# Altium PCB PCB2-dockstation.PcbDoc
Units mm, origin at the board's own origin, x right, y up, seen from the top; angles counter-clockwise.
Board outline 98 x 71.5 mm, 2 copper layers (Top Layer, Bottom Layer), stack 1.4 mm thick; 17 components, 28 nets, 47 pads, 4 vias.
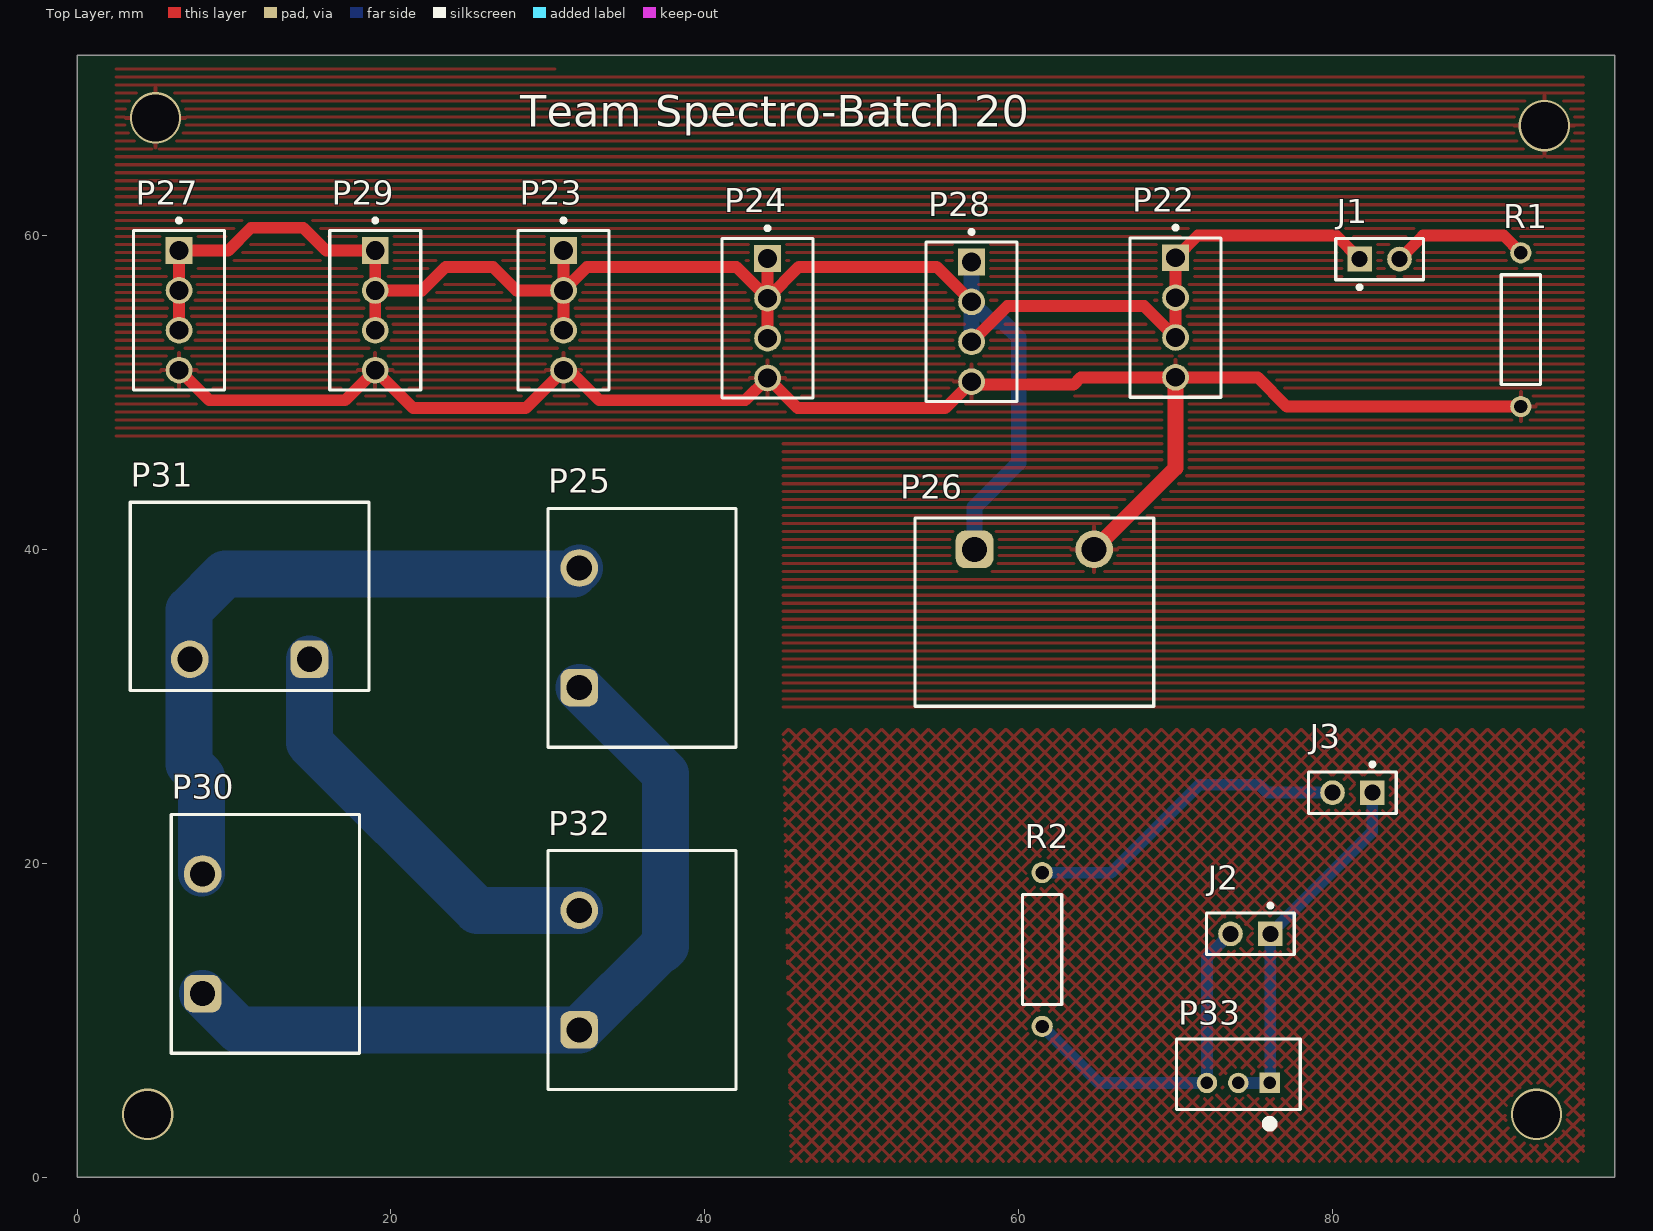
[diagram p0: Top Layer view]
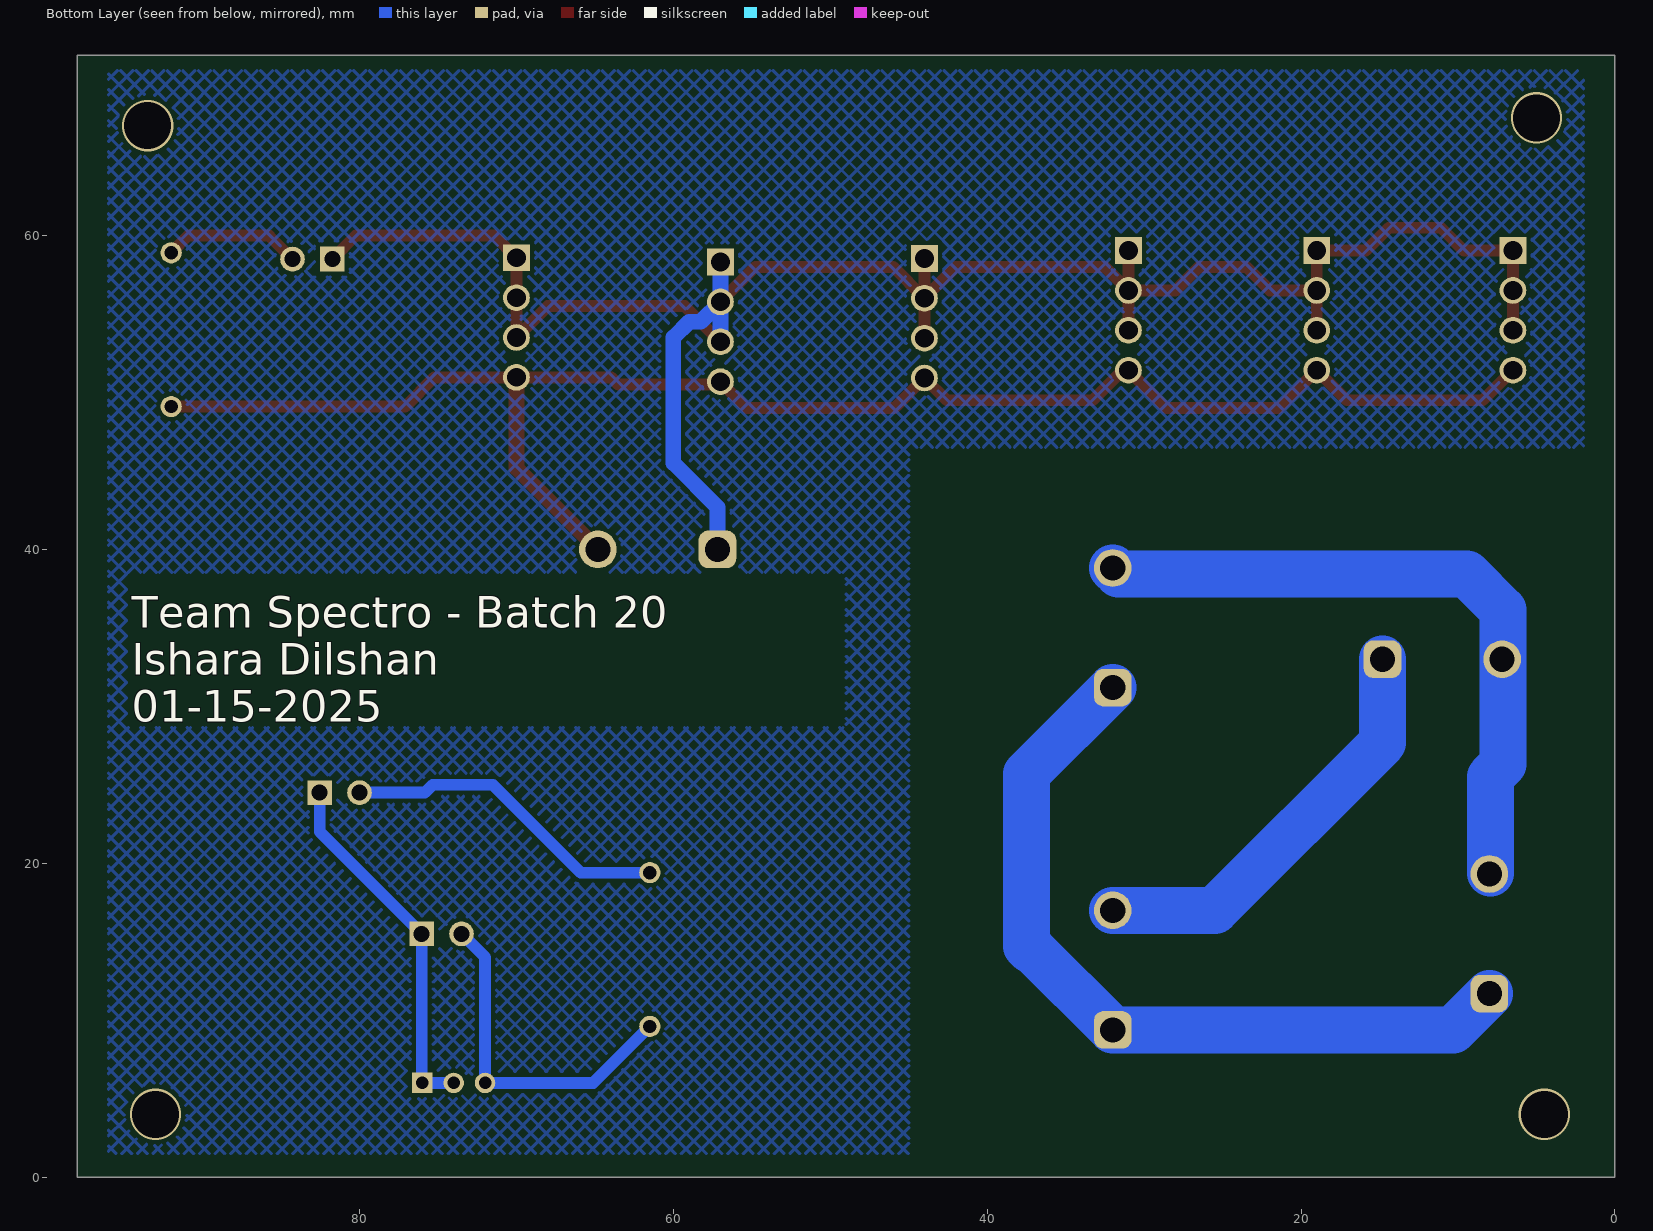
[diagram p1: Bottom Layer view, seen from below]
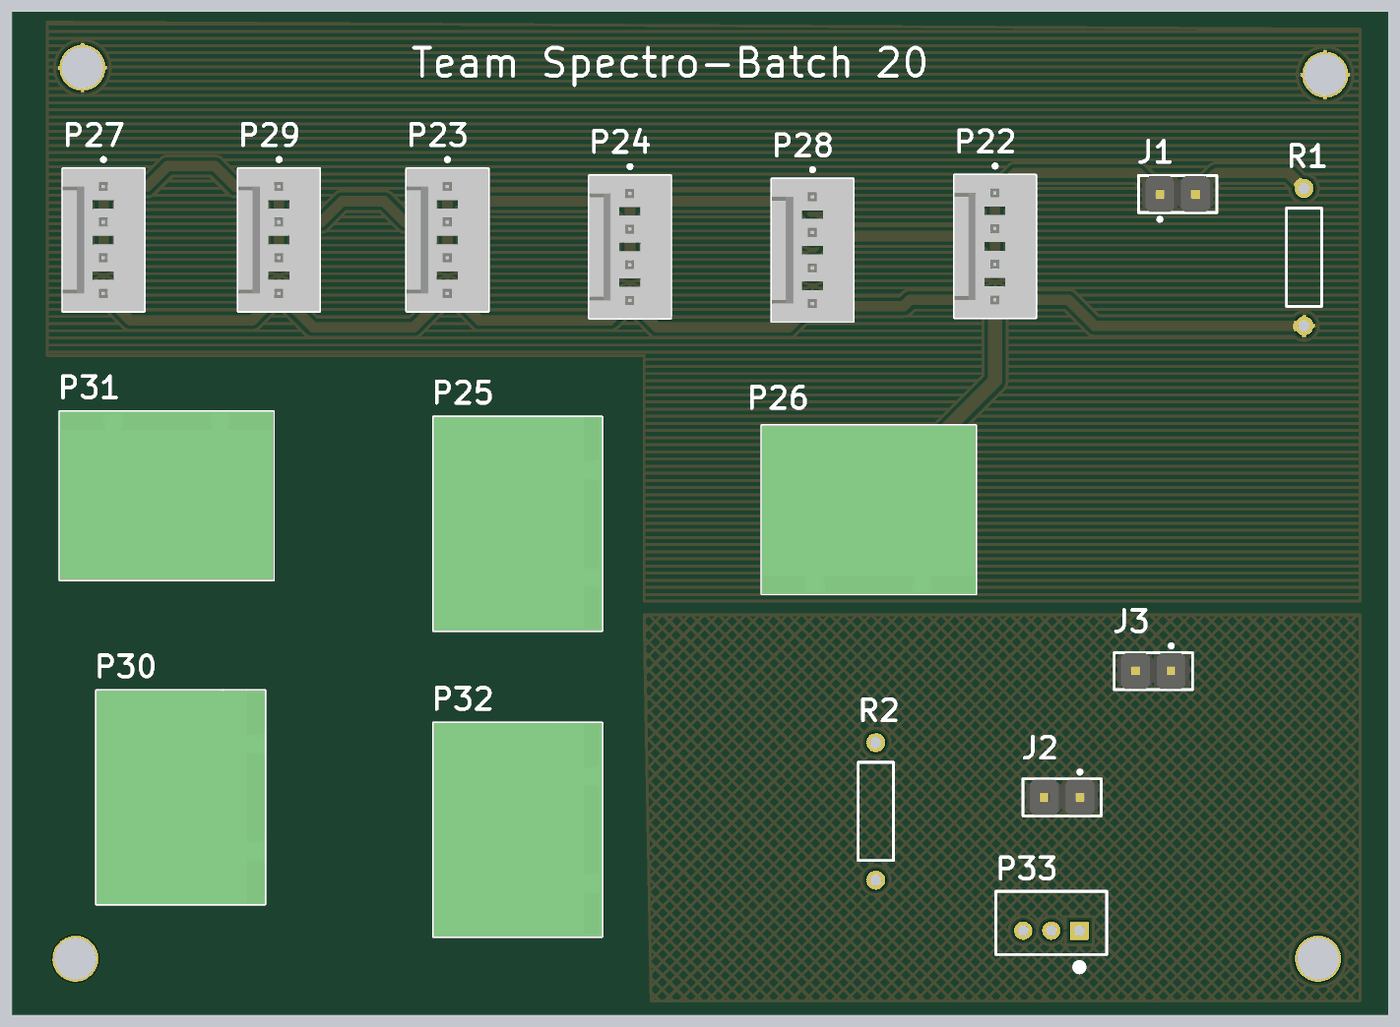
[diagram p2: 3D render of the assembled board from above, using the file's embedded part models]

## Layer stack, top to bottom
Top Solder: solder mask 0.0502, Solder Resist, Dk 3.5
Top Layer: signal copper 0.1
Dielectric 1: dielectric 1.2004, FR-4, Dk 4.8
Bottom Layer: signal copper 0.1
Bottom Solder: solder mask 0.0502, Solder Resist, Dk 3.5

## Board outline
0,0 98,0 98,71.5 0,71.5

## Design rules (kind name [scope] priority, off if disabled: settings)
Clearance [All] p1: gap=0.254 ignorepadtopadclearanceinfootprint=FALSE except(0: Arc-Hole Track-Hole SMDPad-Hole THPad-Hole Via-Hole Fill-Hole Poly-Hole Region-Hole Text-Hole)
PolygonConnect [All] p1: connectstyle=Relief reliefconductorwidth=0.254 reliefentries=4 polygonreliefangle="90 Angle" airgapwidth=0.254
RoutingVias [All] p1: holewidth=1 width=1.27 viastyle="Through Hole" minholewidth=1 minwidth=1.27 maxholewidth=1 maxwidth=1.27
SolderMaskExpansion [All] p1: expansion=0.102 istentingtop=FALSE
Width [All] p1: maxlimit=3 minlimit=0.1 preferedwidth=0.254 minimp=50.000000 maximp=50.000000 favimp=50.000000
30 further rules are at their usual default settings.

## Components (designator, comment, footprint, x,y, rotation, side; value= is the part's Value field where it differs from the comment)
J1 "LED-01" FP-M20-9990245-MFG 83,58.5 r0 top
J2 "Relay-Signal" FP-M20-9990245-MFG 74.77,15.5 r180 top
J3 "LED-02" FP-M20-9990245-MFG 81.27,24.5 r180 top
P22 "IR1" MOLX-22-27-2041_V 70,54.77 r90 top
P23 "IR2" MOLX-22-27-2041_V 31,55.23 r90 top
P24 "IR3" MOLX-22-27-2041_V 44,54.73 r90 top
P25 "Step-Down-In" 691313410002 36,35 r90 top
P26 "Step-Down-Out" 691313410002 61,36 r0 top
P27 "IR4" MOLX-22-27-2041_V 6.5,55.23 r90 top
P28 "IR5" MOLX-22-27-2041_V 57,54.5 r90 top
P29 "IR6" MOLX-22-27-2041_V 19,55.23 r90 top
P30 "PowerIN" 691313410002 12,15.5 r90 top
P31 "Dock-Out" 691313410002 11,37 r180 top
P32 "Relay-In/Out" 691313410002 36,13.19 r90 top
P33 "Relay" JST-B3B-PH-K-S-3_V 74,6.55 r180 top
R1 "OD103JE" OMTE-RES7X2.5-2 92,54 r90 top
R2 "OD103JE" OMTE-RES7X2.5-2 61.5,14.5 r270 top

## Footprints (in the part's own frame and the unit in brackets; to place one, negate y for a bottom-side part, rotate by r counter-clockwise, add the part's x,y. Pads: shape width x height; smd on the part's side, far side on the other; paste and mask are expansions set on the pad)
691313410002 [mm] "7.62 mm - Closed Horizonal PCB Header - 2p"
  rrect50% 2.4x2.4 hole 1.6: 1(-3.81,4)
  round 2.4 hole 1.6: 2(3.81,4)
  silkscreen extent -7.61,-6 7.61,6, body extent -7.62,-6 7.62,6, height 8.55
FP-M20-9990245-MFG [mm]
  rect 1.57x1.57 hole 1.02 paste-1000 mask+0: 1(-1.27,0)
  round 1.57 hole 1.02 paste-1000 mask+0: 2(1.27,0)
  silkscreen extent -2.79,-1.92 2.79,1.32, body extent -2.89,-1.42 2.89,1.42, height 0.25
JST-B3B-PH-K-S-3_V [mm] "Connector, 3-Leads, Body 7.9x4.5mm, Pitch 2mm"
  rect 1.3x1.3 hole 0.8: 1(-2,0.55)
  round 1.3 hole 0.8: 2(0,0.55) 3(2,0.55)
  silkscreen extent -3.95,-2.25 3.95,3.4, body extent -3.95,-2.25 3.95,2.25, height 6
MOLX-22-27-2041_V [mm] "CONN, 4-Leads, Body 10.16x5.8mm, Pitch 2.54mm"
  rect 1.7x1.7 hole 1.19: 1(3.81,0)
  round 1.7 hole 1.19: 2(1.27,0) 3(-1.27,0) 4(-3.81,0)
  silkscreen extent -5.08,-2.9 5.85,2.9, body extent -5.08,-2.9 5.08,2.9, height 11.7
OMTE-RES7X2.5-2 [mm] "Resistor, Axial; Body 7x2.5mm, Lead Dia. 0.6mm"
  round 1.35 hole 0.85: 1(-4.9,0) 2(4.9,0)
  silkscreen extent -3.5,-1.25 3.5,1.25, body extent -3.5,-1.25 3.5,1.25, height 2.5

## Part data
J1 J2 J3: library part CMP-15831-000105-1, "CONN HEADER VERT 2POS 2.54MM", Case/Package=SIL, Color=Black, Contact Resistance=25mR, Current=3A, Flammability Rating="UL94 V-0", Insulation Resistance=10GR, Max Operating Temperature=105°C, Min Operating Temperature=-40°C, Package Quantity=1000, Voltage=50V, Voltage Rating (AC)=750V
P22 P23 P24 P27 P28 P29: library part CMP-2000-05243-1, "Male Header, Pitch 2.54 mm, 1 x 4 Position, Height 11.7 mm, Tail Length 3.56 mm, RoHS, Bulk", Current Rating=4A, Manufacturer=Molex, Operating Temperature=0degCto+75degC, Voltage Rating=250V
P25 P26 P30 P31 P32: library part CMP-1502-02424-2, Color=Green, Current=20A, Voltage=300V
P33: library part CMP-2000-05164-1, "Male Header, Pitch 2 mm, 1 x 3 Position, Height 6 mm, Tail Length 3.4 mm, -25 to 85 degC, RoHS, Bulk", Manufacturer=JST
R1 R2: library part CMP-2000-06865-1, "Little Demon(R) Carbon Composition Molded OD Series, 250 V, 10 KOhm, +/-5%, -70 to 130 degC, 2-Pin THD, RoHS, Bulk", Manufacturer=Ohmite, Operating Temperature=-, Package / Case=Axial, Package Description="2-Pin THD Resistor, Body 7 x 2.5 mm, Lead Dia. 0.6 mm", Package Reference=RES7X2.5, Power (Watts)=0.25W,1/4W, Power Rating=0.25W, Resistance (Ohms)=10k, Standard Package=100, Tolerance=±5%

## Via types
v1: diameter 3.27, hole 3, Top Layer to Bottom Layer, 4 vias

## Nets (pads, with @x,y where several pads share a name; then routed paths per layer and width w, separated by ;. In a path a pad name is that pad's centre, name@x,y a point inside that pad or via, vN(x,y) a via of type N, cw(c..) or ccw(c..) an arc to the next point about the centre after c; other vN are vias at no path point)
5V: 
B+: 
B-: 
C1+: 
C2+: 
C3+: 
GND: P25.2 P30.2 P31.2 | length 43
  Bottom Layer w3: P31.2@7.133,32.943 7.133,26.31 7.943,25.5 P30.2@7.943,19.367 ; P31.2@7.133,33.057 7.133,36.133 9.443,38.443 31.633,38.443 P25.2
NetC1_1: 
NetC1_2: 
NetJ1_2: J1.2 R1.2 | length 8.8
  Top Layer w0.75: J1.2 85.77,60 90.9,60 R1.2
NetJ3_2: J3.2 R2.1 | length 21
  Bottom Layer w0.75: R2.1 65.9,19.4 71.5,25 75.339,25 75.839,24.5 J3.2
NetP7_2: 
NetP8_2: 
NetP9_2: 
NetP10_2: 
NetP11_2: 
NetP12_2: 
NetP13_2: 
NetP14_2: 
P-IN-dock: P25.1 P30.1 P32.1 | length 51.4
  Bottom Layer w3: P30.1 10.31,9.38 P32.1 37.12,14.5 37.277,14.5 37.5,14.723 37.5,25.69 P25.1
P-REL-OUT: P31.1 P32.2 | length 26.9
  Bottom Layer w3: P31.1 14.81,27.69 25.5,17 P32.2
Rel2-Signal: 
S1: 
S2: 
SD5: J1.1 P22.1 P22.2 P22.3 P23.1 P23.2 P23.3 P24.1 P24.2 P24.3 P26.1 P27.1 P27.2 P27.3 P28.1 P28.2 P28.3 P29.1 P29.2 P29.3 | length 132.9
  Top Layer w0.75: P27.3 P27.2 P27.1 9.625,59.04 11.085,60.5 14.415,60.5 15.875,59.04 P29.1 P29.2 ; P29.3 P29.2 ; P23.3 P23.2 ; P23.1 P23.2 ; P24.3 P24.2 ; P24.1 P24.2 ; P28.3 59.27,55.5 68,55.5 P22.3 P22.2 P22.1 71.42,60 80.23,60 J1.1 ; P28.2 54.77,58 46,58 P24.2 ; P29.2 22,56.5 23.5,58 26.5,58 28,56.5 P23.2 ; P23.2 32.5,58 42,58 P24.2
  Bottom Layer w1: P28.3 P28.2 ; P28.1 P28.2 ; P26.1 57.19,42.69 60,45.5 60,53.5 58.991,54.509 58.261,54.509 P28.2
SDG: P22.4 P23.4 P24.4 P26.2 P27.4 P28.4 P29.4 R1.1 | length 106.1
  Top Layer w0.75: P27.4 8.42,49.5 17.08,49.5 P29.4 21.42,49 28.58,49 P23.4 31.357,51.42 33.277,49.5 42.58,49.5 P24.4 45.92,49 55.31,49 P28.4 57.19,50.5 63.5,50.5 63.96,50.96 P22.4 75.24,50.96 77.1,49.1 R1.1
  Top Layer w1: P26.2 70,45.19 P22.4
  other v1: 93.5,67 5,67.5
SR5: J2.1 J3.1 P33.1 P33.2 | length 23.2
  Bottom Layer w0.75: P33.2 P33.1 76.04,6.04 J2.1 82.54,22 J3.1
SRG: J2.2 P33.3 R2.2 | length 22.1
  Bottom Layer w0.75: R2.2 65.1,6 P33.3 72,14 J2.2
copper on no net:
  other v1: 4.5,4 93,4

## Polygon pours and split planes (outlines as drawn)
P-REL-OUT on Bottom Solder "NONET_L-01_P-001" (solid): 17.5,34.5 17.5,28.5 26,20 33.5,20 33.5,19.5 33.5,19 33.5,14.5 23,14.5 12.5,25 12.5,34.5
P-IN-dock on Bottom Solder "NONET_L-01_P-001" (solid): 10.5,14 12.5,12 32,12 35.5,15.5 35.5,25 28.5,32 28.5,33.5 35.5,33.5 41.5,27.5 41.5,11 36,5.5 11.5,5.5 3,14
GND on Bottom Solder "NONET_L-01_P-001" (solid): 9.5,18 9,18 5.5,18 5.5,24 4.5,26 4.5,27 4.5,41.5 34.5,41.5 34.5,41 34.5,40.5 34.5,36.5 12,36.5 10.5,35 10.5,18
no net on Top Layer "NONET_L01_P001" (hatched 45Degree grid 0.7 track 0.203, pour order 1): 45,28.5 96,28.5 96,1 95.5,1 45.5,1
SDG on Top Layer "SDG_L01_P000" (hatched Horizontal grid 0.508 track 0.203, pour order 0): 2.5,70.751 2.5,48 2.5,47.5 2.5,47 45,47 45,29.5 96,29.5 96,70.251
no net on Bottom Layer "NONET_L02_P002" (hatched 45Degree grid 0.7 track 0.203, pour order 2): 2,70.5 96,70.5 96,1.5 45,1.5 45,46.5 2,46.5

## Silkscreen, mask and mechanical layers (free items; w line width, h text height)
Top Overlay:
  text "Team Spectro-Batch 20" at 28.254,66.92 h2
Bottom Overlay:
  text "Team Spectro - Batch 20 / Ishara Dilshan / 01-15-2025" at 94.5,29 h2
Mechanical 1:
  the board outline again, w0.2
